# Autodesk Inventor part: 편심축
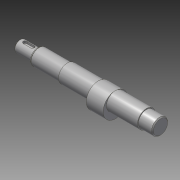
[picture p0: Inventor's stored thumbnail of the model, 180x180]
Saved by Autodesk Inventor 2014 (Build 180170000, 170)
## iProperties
Created: 2017-08
Part Number: 편심축
Material: 강철, 연강
Document SubType Name: Modeling
Designer: mduedu
Density: 1 g/cm^3
Appearance: 강철
Author: mduedu
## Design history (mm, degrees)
sketch "스케치1"
  geometry: L1 (0, 0)-(150, 0); L2 (150, 0)-(150, 8.5); L3 (150, 8.5)-(135, 8.5); L4 (135, 8.5)-(135, 9.5); L5 (135, 9.5)-(51, 9.5); L6 (51, 9.5)-(51, 8.5); L7 (51, 8.5)-(19, 8.5); L8 (19, 8.5)-(19, 6); L9 (19, 6)-(0, 6); L10 (0, 6)-(0, 0)
  constraints: 20 end point, 6 parallel, 2 collinear, 2 perpendicular, 1 horizontal
  dimensions: "d0" = 150 distance of L1.start L1.end; "d1" = 17 diameter of L3 L1; "d2" = 19 diameter of L5 L1; "d3" = 12 diameter of L9 L1; "d4" = 19 distance of L8.end L9.end; "d5" = 15 distance of L2.end L3.end; "d6" = 84 distance of L4.end L5.end
revolve "회전1" sketch "스케치1" stored, may be unused: angle "d7" = 90 deg
node "작업 평면1"
sketch "스케치2"
  geometry: C1 r 9.5 at (0, 0) reference; C2 r 13 at (0, -3.5); 1 further point
  constraints: 1 centre point, 1 tangent, 1 vertical alignment
  dimensions: "d8" = 3.5 distance of point (0, 0) C2.centre
extrude "돌출1" join sketch "스케치2" stored distance "d9" = 18; taper "d10" = 0 deg
chamfer "모따기1" distance "d11" = 1; stored, may be unused: second distance "d12" = 2, angle "d13" = 45 deg
node "작업 평면2"
sketch "스케치3"
  geometry: L1 (3.5, -2)-(-4.5, -2); L2 (-4.5, -2)-(-4.5, 2); L3 (-4.5, 2)-(3.5, 2); L4 (3.5, 2)-(3.5, -2); L5 (9.5, 6)-(9.5, -6) reference; A1 r 2 centre (3.5, 0) between (3.5, -2) and (3.5, 2); A2 r 2 centre (-4.5, 0) between (-4.5, 2) and (-4.5, -2); A3 r 2 centre (3.5, 0) between (3.5, 2) and (3.5, -2); A4 r 2 centre (-4.5, 0) between (-4.5, -2) and (-4.5, 2); 1 further point
  constraints: 8 end point, 8 point on circle, 4 centre point, 2 midpoint, 2 parallel, 1 horizontal, 1 horizontal alignment, 1 perpendicular
  dimensions: "d14" = 12 dimension on A2 A1; "d16" = 4 distance between parallel lines of L3 L1; "d17" = 4 distance edge to line of A1 L5
extrude "돌출2" cut sketch "스케치3" distance "d18" = 2.5; taper "d19" = 0 deg
chamfer "모따기2" distance "d20" = 1; stored, may be unused: second distance "d21" = 2, angle "d22" = 45 deg
chamfer "모따기3" distance "d23" = 1; stored, may be unused: second distance "d24" = 2, angle "d25" = 60 deg
fillet "모깎기1" dims "d26" = 0.5
hole "구멍1" diameter "d29" = 3.242; stored, may be unused: countersink angle "d33" = 90 deg, drill point angle "d35" = 118 deg; dims "d30" = 8, "d31" = 4, "d32" = 2, "d34" = 10, "d48" = 10, "d49" = 10
sketch "스케치4"
  geometry: L1 (13.5, -6)-(15, -4.5); L2 (15, -4.5)-(16.5, -6); L3 (15, -6)-(13.5, -6); L4 (15, -6)-(15, -4.5); L5 (1, -6)-(19, -6) reference; L6 (19, -6)-(19, 6) reference; 1 further point
  constraints: 8 end point, 1 collinear, 1 horizontal, 1 point on line, 1 vertical, 1 other
  dimensions: "d42" = 4 distance between parallel lines of L6 L4; "d43" = 3 distance of L1.start L2.end; "d44" = 90 deg angle of L1 L2
revolve "회전2" sketch "스케치4" stored, may be unused: angle "d45" = 90 deg
node "작업점1"
node "솔리드1"
node "절단 모서리 투영1"
other parameters: "d38" = -42
